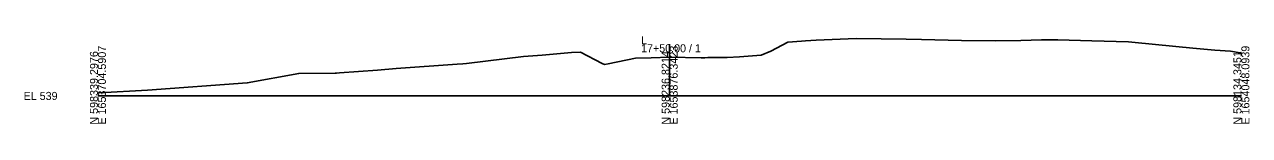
# Model space of a CAD drawing. Extents: x -26 to 403, y -10 to 6021.
# Drawn here: x -25.7 to 402.8, y 5990.3 to 6020.8 of the extents above; entities that cross this region are included whole.
import ezdxf

# ---------------------------------------------------------------- set-up
doc = ezdxf.new("R2010")
doc.units = 0
for name, color, linetype in [('Default', 7, 'Continuous'), ('Exist Cross Section Cell', 7, 'Continuous'), ('Exist XS Ground Line', 7, 'Continuous')]:
    doc.layers.add(name, color=color, linetype=linetype)

msp = doc.modelspace()

# ---------------------------------------------------------------- linework, layer by layer
at = {"layer": 'Exist Cross Section Cell'}
for p, q in [((200, 6000), (200, 6017.99)), ((0, 6000), (200, 6000)), ((200, 6000), (400, 6000))]:
    msp.add_line(p, q, dxfattribs=at)
at = {"layer": 'Exist XS Ground Line'}
msp.add_lwpolyline([(0, 6001), (0.43, 6001.04), (17.32, 6002.04), (52.24, 6004.55), (70.26, 6007.85), (83.04, 6007.96), (83.44, 6007.96), (84.54, 6008.06), (97.75, 6008.95), (104.38, 6009.57), (125.72, 6011.07), (127.7, 6011.22), (128.88, 6011.35), (148.83, 6013.76), (155.36, 6014.24), (165.68, 6015.15), (168.81, 6015.26), (176.34, 6011.33), (177.19, 6010.97), (178.47, 6011.2), (188.09, 6013.13), (193.57, 6013.31), (199.93, 6013.53), (200, 6013.52), (211.05, 6013.29), (211.91, 6013.27), (211.92, 6013.26), (212.31, 6013.29), (213.32, 6013.36), (220.15, 6013.42), (224.42, 6013.59), (232.02, 6014.24), (235.38, 6015.56), (241.3, 6018.69), (246.17, 6019.07), (247.55, 6019.24), (251.2, 6019.42), (265.2, 6020.01), (282.75, 6019.78), (288.13, 6019.63), (302.05, 6019.35), (313.98, 6019.15), (322.86, 6019.35), (330.05, 6019.56), (335.74, 6019.52), (347.66, 6019.14), (360.56, 6018.81), (362.8, 6018.65), (383.05, 6016.65), (390.71, 6015.95), (396.18, 6015.54), (399.55, 6015.02), (400, 6015.03)], dxfattribs=at)

# ---------------------------------------------------------------- texts
at = {"layer": 'Default'}
msp.add_text('-', height=0.0001, dxfattribs=at).set_placement((0, 6000))
at = {"layer": 'Exist Cross Section Cell'}
for s, p in [('E 1653704.5907', (2.8, 5990)), ('E 1653876.3423', (202.8, 5990)), ('E 1654048.0939', (402.8, 5990)), ('N 598339.2976', (0, 5990)), ('N 598236.8214', (200, 5990)), ('N 598134.3451', (400, 5990))]:
    msp.add_text(s, height=2.8, rotation=90, dxfattribs=at).set_placement(p)
for s, p in [('17+50.00 / 1', (190, 6015.19)), ('L', (190, 6017.99)), ('EL 539', (-26, 5998.6))]:
    msp.add_text(s, height=2.8, dxfattribs=at).set_placement(p)

doc.saveas('drawing.dxf')
